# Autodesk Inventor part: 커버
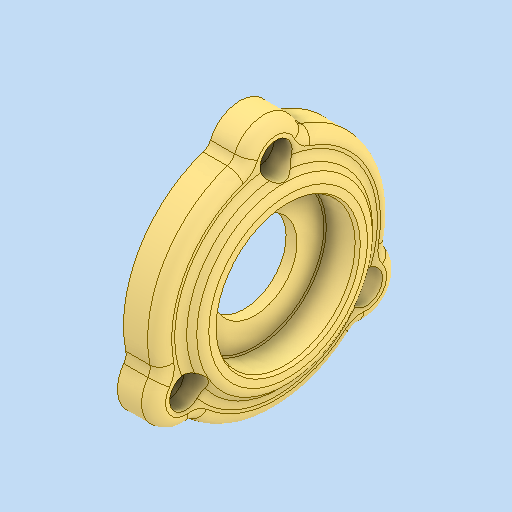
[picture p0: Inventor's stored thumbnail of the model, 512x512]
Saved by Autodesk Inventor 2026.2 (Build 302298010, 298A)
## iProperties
Created: 2026-03
Part Number: 커버
Material: 알루미늄 6061
Document SubType Name: Modeling
Designer: PC-2-06
Density: 2.7 g/cm^3
Appearance: 기본값
Author: jhkim
Sending System: Autodesk Inventor 2026
Preprocessor: ST-DEVELOPER v20.1
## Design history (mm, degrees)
feature "솔리드1"
node "솔리드2"
